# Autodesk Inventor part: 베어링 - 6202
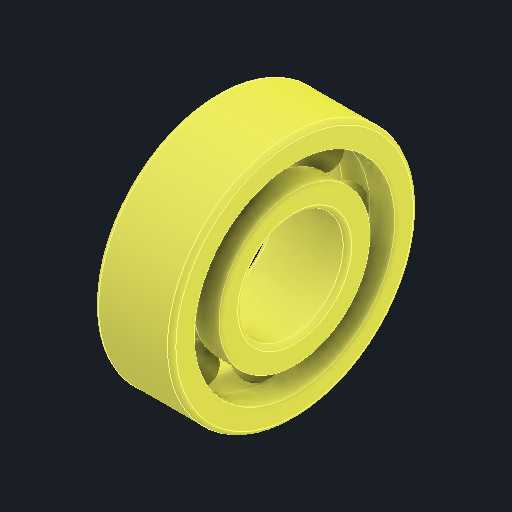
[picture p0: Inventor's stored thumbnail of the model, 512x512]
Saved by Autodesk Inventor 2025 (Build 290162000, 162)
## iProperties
Created: 2025-08
Part Number: 베어링 - 6202
Material: 강, 연강
Description: 깊은 그루브 볼 베어링
Document SubType Name: Modeling
Designer: infra002
Density: 7.86 g/cm^3
Appearance: 기본값
Author: jhkim
Sending System: Autodesk Inventor 2026
Preprocessor: ST-DEVELOPER v20.1
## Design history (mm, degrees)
feature "Solid1"
feature "Solid1:1"
feature "Solid1:2"
feature "Solid1:3"
feature "Solid1:4"
feature "Solid1:5"
feature "Solid1:6"
feature "Solid1:7"
feature "Solid1:8"
feature "Solid1:9"
node "솔리드1"
node "솔리드2"
node "솔리드3"
node "솔리드4"
node "솔리드5"
node "솔리드6"
node "솔리드7"
node "솔리드8"
node "솔리드9"
node "솔리드10"
